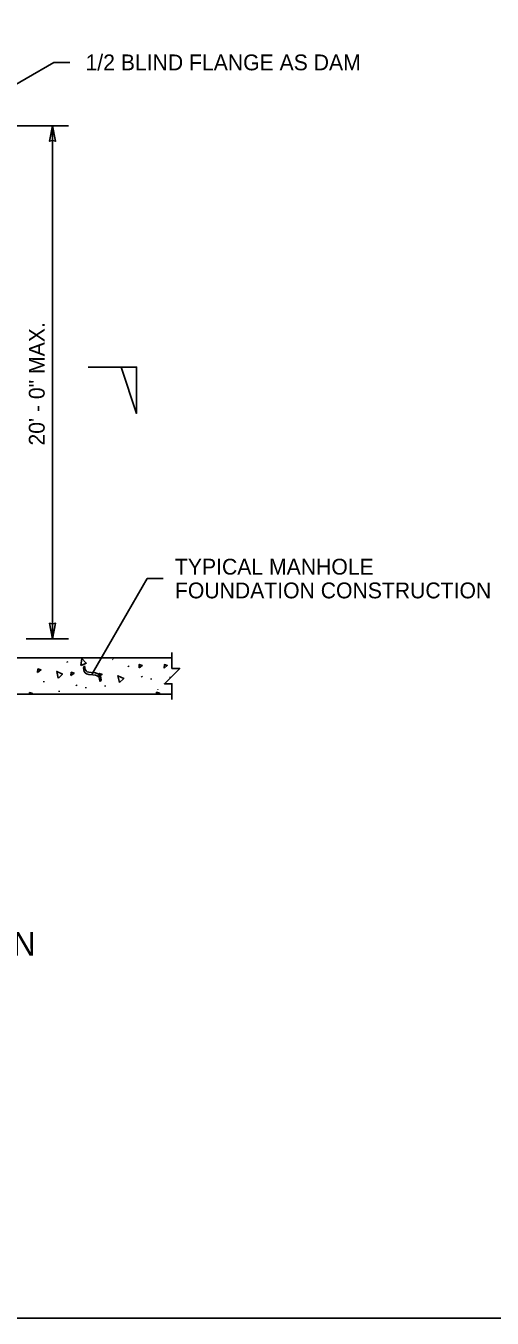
# Model space of a CAD drawing. Extents: x 99862 to 103151, y 100000 to 102076.
# Drawn here: x 100803 to 101274, y 100000 to 101305 of the extents above; entities that cross this region are included whole.
import ezdxf

# ---------------------------------------------------------------- set-up
doc = ezdxf.new("R2010")
doc.units = 0
for name, color, linetype in [('Level 1', 7, 'Continuous'), ('Level 15', 7, 'Continuous'), ('Level 17', 7, 'Continuous'), ('Level 19', 7, 'Continuous'), ('Level 20', 7, 'Continuous'), ('Level 9', 7, 'Continuous')]:
    doc.layers.add(name, color=color, linetype=linetype)

msp = doc.modelspace()

# ---------------------------------------------------------------- linework, layer by layer
at = {"layer": 'Level 1'}
for p, q in [((100745.8, 100666.7), (100950.5, 100666.7)), ((100721.8, 100630), (100950.5, 100630))]:
    msp.add_line(p, q, dxfattribs=at)
msp.add_lwpolyline([(99862, 99999.5), (103151, 99999.5), (103151, 102075.5), (99862, 102075.5)], close=True, dxfattribs=at)
at = {"layer": 'Level 15'}
for p, q in [((100774.8, 101236), (100831.1, 101268.5)), ((100831.1, 101268.5), (100847.1, 101268.5)), ((100791.8, 101204.5), (100845.8, 101204.5)), ((100829.8, 101204.5), (100829.8, 100686)), ((100869.9, 100650.7), (100925.5, 100746.9)), ((100925.5, 100746.9), (100941.5, 100746.9)), ((100803.2, 100686), (100845.8, 100686))]:
    msp.add_line(p, q, dxfattribs=at)
for points in [[(100829.8, 101204.5), (100832.9, 101188.8), (100829.8, 101189.5), (100826.7, 101188.8)], [(100829.8, 100686), (100832.9, 100701.7), (100829.8, 100701), (100826.7, 100701.7)]]:
    msp.add_lwpolyline(points, close=True, dxfattribs=at)
msp.add_lwpolyline([(100950.5, 100672.1), (100950.5, 100656.1), (100958.3, 100656.1), (100942.8, 100640.6), (100950.5, 100640.6), (100950.5, 100624.6)], dxfattribs=at)
at = {"layer": 'Level 17'}
for p, q in [((100808.5, 100630.5), (100808.5, 100630)), ((100842.5, 100630.5), (100842.5, 100630)), ((100936.3, 100634.9), (100936.3, 100634.4))]:
    msp.add_line(p, q, dxfattribs=at)
at = {"layer": 'Level 19'}
for p, q in [((100844.5, 100663.1), (100845, 100662.1)), ((100890.5, 100665.6), (100891.2, 100665.1)), ((100906.3, 100658.7), (100906.8, 100657.7)), ((100820.9, 100642.1), (100821, 100643.3)), ((100853.7, 100639.6), (100854.2, 100638.6)), ((100863.3, 100636), (100863.3, 100637.3)), ((100882.8, 100637.7), (100882.8, 100638.9)), ((100919.7, 100648.3), (100920.2, 100647.3)), ((100929.3, 100644.8), (100929.3, 100646)), ((100948.8, 100646.5), (100948.8, 100647.7)), ((100836.5, 100632.4), (100836.6, 100633.6))]:
    msp.add_line(p, q, dxfattribs=at)
for points in [[(100858.5, 100658.9), (100859.5, 100666), (100863.9, 100661.4), (100858.6, 100659)], [(100814.7, 100652.1), (100815, 100655.5), (100818, 100654.6), (100814.7, 100652.1)], [(100835.6, 100646.1), (100834.1, 100653.1), (100839.8, 100650.3), (100835.7, 100646.1)], [(100848.2, 100648.8), (100848.6, 100652.2), (100851.5, 100651.3), (100848.2, 100648.8)], [(100876.5, 100647.7), (100876.9, 100651.1), (100879.8, 100650.2), (100876.5, 100647.7)], [(100897.4, 100641.7), (100895.9, 100648.7), (100901.7, 100645.9), (100897.5, 100641.7)], [(100917.2, 100656.7), (100917.5, 100660.1), (100920.5, 100659.2), (100917.2, 100656.7)], [(100942.5, 100656.4), (100942.8, 100659.9), (100945.8, 100659), (100942.5, 100656.4)], [(100806.3, 100630), (100806.5, 100631.7), (100809.4, 100630.8), (100808.4, 100630)], [(100934.9, 100630.4), (100935, 100632), (100938, 100631.1), (100937, 100630.4)]]:
    msp.add_lwpolyline(points, dxfattribs=at)
at = {"layer": 'Level 20'}
for p, q in [((100862, 100658.6), (100860.9, 100656.8)), ((100860.9, 100656.8), (100861.3, 100654.7)), ((100861.3, 100654.7), (100861.9, 100653)), ((100861.9, 100653), (100862.9, 100651.7)), ((100862.9, 100655), (100862, 100658.6)), ((100863.8, 100653.7), (100862.9, 100655)), ((100862.9, 100651.7), (100864.2, 100650.7)), ((100864.9, 100652.7), (100863.8, 100653.7)), ((100864.2, 100650.7), (100866.5, 100649.8)), ((100866.3, 100652.2), (100864.9, 100652.7)), ((100868.7, 100652), (100866.3, 100652.2)), ((100866.5, 100649.8), (100870.6, 100649.5)), ((100873.1, 100651.6), (100868.7, 100652)), ((100870.6, 100649.5), (100873.1, 100649.3)), ((100875.7, 100650.7), (100873.1, 100651.6)), ((100873.1, 100649.3), (100874.9, 100648.7)), ((100874.9, 100648.7), (100876, 100647.9)), ((100877.1, 100649.6), (100875.7, 100650.7)), ((100878.1, 100648.3), (100877.1, 100649.6)), ((100876, 100647.9), (100876.8, 100646.8)), ((100876.8, 100646.8), (100877.4, 100645.1)), ((100877.4, 100645.1), (100877.9, 100642.8)), ((100877.9, 100642.8), (100879, 100644.6)), ((100878.7, 100646.6), (100878.1, 100648.3)), ((100879, 100644.6), (100878.7, 100646.6))]:
    msp.add_line(p, q, dxfattribs=at)
at = {"layer": 'Level 9'}
msp.add_line((100865.8, 100960.6), (100914.7, 100960.6), dxfattribs=at)
msp.add_lwpolyline([(100899.2, 100960.6), (100914.7, 100913.7), (100914.7, 100960.6)], close=True, dxfattribs=at)

# ---------------------------------------------------------------- texts
at = {"layer": 'Level 20'}
for s, height, p in [('1/2 BLIND FLANGE AS DAM', 16, (100863.1, 101260.5)), ('TYPICAL MANHOLE', 16, (100953.5, 100750.9)), ('FOUNDATION CONSTRUCTION', 16, (100953.5, 100726.9)), ('DROP CONNECTION', 24, (100495.4, 100365.8))]:
    msp.add_text(s, height=height, dxfattribs=at).set_placement(p)
msp.add_text('20\' - 0" MAX.', height=16, rotation=90, dxfattribs=at).set_placement((100821.8, 100881.3))

doc.saveas('drawing.dxf')
